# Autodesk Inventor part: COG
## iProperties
Created: 2008-06
Part Number: COG
Document SubType Name: Modeling
Designer: CADCIM
Mass: 866.025 g
Surface Area: 519.615 cm^2
Volume: 866.025 cm^3
Density: 1 g/cm^3
Author: CADCIM
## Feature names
1. Extrusion1
